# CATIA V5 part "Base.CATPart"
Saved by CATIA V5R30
Part number: Part1
Bounding box of the stored display mesh (mm): x -50 to 50, y -25 to 25, z 0 to 50
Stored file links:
  D:\PROJECTS\CATIA V56R 2020\Resources\Parts File\c12_catia_v5_6r2020_prt\c12_catia_v5-6r2020 figr_12-8\Base.CATPart
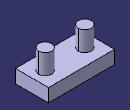
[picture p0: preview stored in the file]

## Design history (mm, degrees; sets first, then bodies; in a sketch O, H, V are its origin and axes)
Body1 (main body)
  Sketch1 on xy-plane, origin (0, 0, 0), H (1, 0, 0), V (0, 1, 0)
    line L1 (50, 25) -> (50, -25)
    line L2 (50, -25) -> (-50, -25)
    line L3 (-50, -25) -> (-50, 25)
    line L4 (-50, 25) -> (50, 25)
    circle A1 centre (-30, 0) radius 10
    point P5 (-30, 0)
    circle A2 centre (30, 0) radius 10
    length L2 = 100
    length L1 = 50
    radius A1 = 10
    distance P5 V = 30
    vertical: L1 V, L3 V
    horizontal: L2 H, L4 H
    equidistance: L1 L3 O, L2 L4 O
    coincidence: P5 H
    symmetry: A1 A2 V
  MultiPad1: profile Sketch1, domains (length 20; length 50; length 50)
